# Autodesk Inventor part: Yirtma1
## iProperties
Created: 2008-12
Part Number: Yirtma1
Material: Default
Document SubType Name: Sheet Metal
Designer: Designer
Density: 1 g/cm^3
Sheet Metal Rule: Default_mm
Author: Designer
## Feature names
1. Bend3
